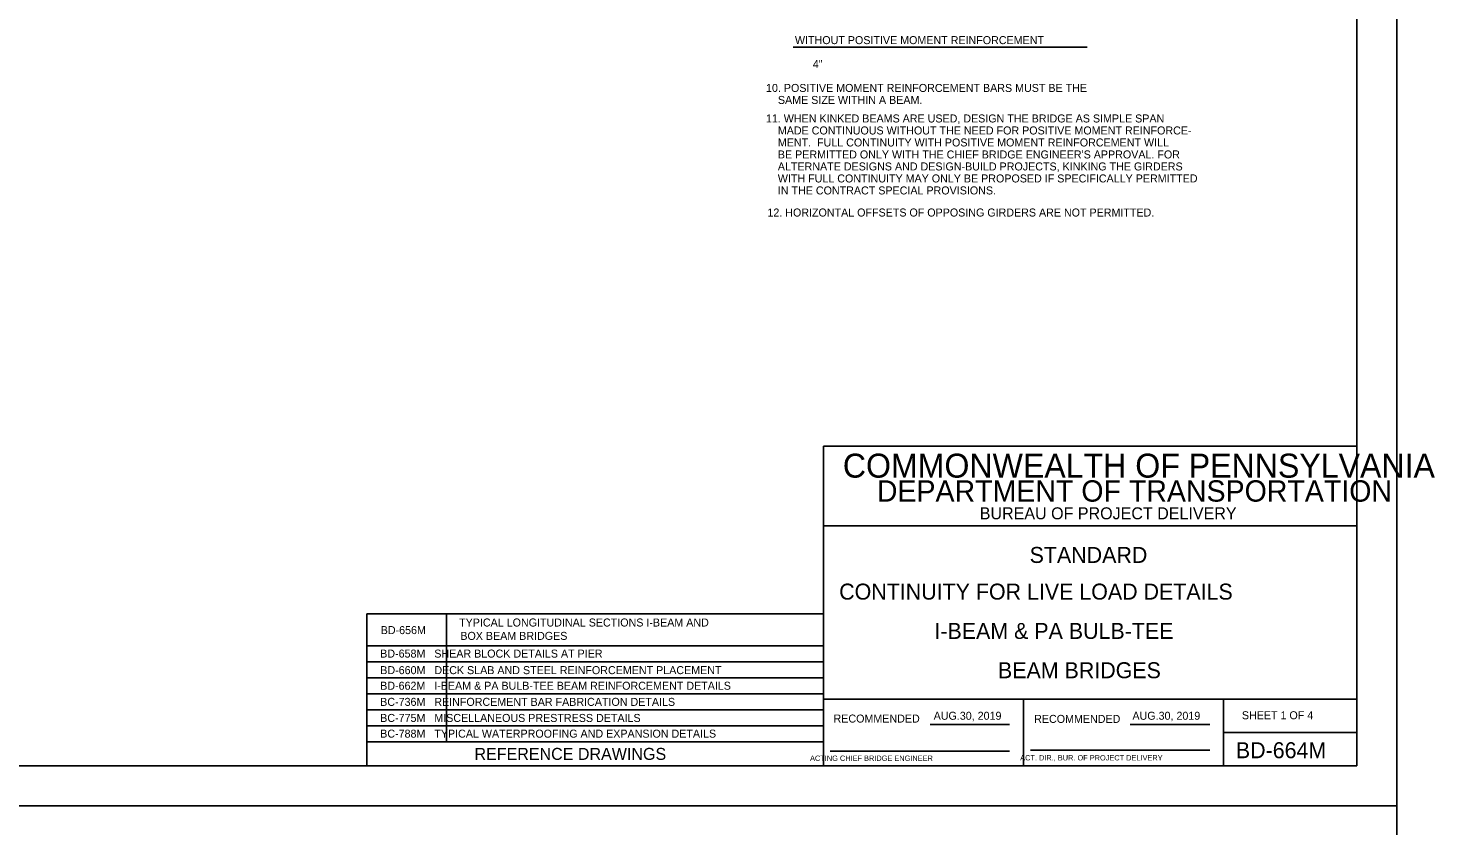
# Model space of a CAD drawing. Extents: x 639980 to 641204, y 298038 to 300414.
# Drawn here: x 640308 to 640836, y 299812 to 300112 of the extents above; entities that cross this region are included whole.
import ezdxf

# ---------------------------------------------------------------- set-up
doc = ezdxf.new("R2010")
doc.units = 0
for name, color, linetype in [('1', 7, 'Continuous'), ('2', 7, 'Continuous'), ('PLT-BNDY', 7, 'Continuous')]:
    doc.layers.add(name, color=color, linetype=linetype)

msp = doc.modelspace()

# ---------------------------------------------------------------- linework, layer by layer
at = {"layer": '2'}
for p, q in [((640806.31, 300398.78), (640806.31, 299834.78)), ((640595, 300104.45), (640705.21, 300104.45)), ((640806.31, 299954.78), (640606.31, 299954.78)), ((640606.31, 299954.78), (640606.31, 299834.78)), ((640806.31, 299834.78), (640806.31, 299954.78)), ((640806.31, 299924.78), (640606.31, 299924.78)), ((640435.1, 299891.78), (640606.31, 299891.78)), ((640435.1, 299891.78), (640435.1, 299834.78)), ((640435.1, 299891.78), (640601.07, 299891.78)), ((640464.97, 299843.78), (640464.97, 299891.78)), ((640435.1, 299879.78), (640606.31, 299879.78)), ((640435.1, 299873.78), (640606.31, 299873.78)), ((640435.1, 299867.78), (640606.31, 299867.78)), ((640435.1, 299861.78), (640606.31, 299861.78)), ((640806.31, 299859.78), (640606.31, 299859.78)), ((640681.31, 299834.78), (640681.31, 299859.78)), ((640756.31, 299859.78), (640756.31, 299834.78)), ((640435.1, 299855.78), (640606.31, 299855.78)), ((640435.1, 299849.78), (640606.31, 299849.78)), ((640646.27, 299850.28), (640676.04, 299850.28)), ((640721.27, 299850.28), (640751.18, 299850.28)), ((640435.1, 299843.78), (640606.31, 299843.78)), ((640756.31, 299847.28), (640806.31, 299847.28)), ((640608.81, 299840.28), (640676.04, 299840.28)), ((640683.93, 299840.66), (640751.18, 299840.66)), ((640806.31, 299834.78), (640020.31, 299834.78)), ((640606.31, 299834.78), (640806.31, 299834.78))]:
    msp.add_line(p, q, dxfattribs=at)
at = {"layer": 'PLT-BNDY'}
for points in [[(639980.31, 300413.78), (640821.31, 300413.78), (640821.31, 299819.78), (639980.31, 299819.78)], [(639980.31, 299819.78), (640821.31, 299819.78), (640821.31, 299225.78), (639980.31, 299225.78)]]:
    msp.add_lwpolyline(points, close=True, dxfattribs=at)

# ---------------------------------------------------------------- texts
at = {"layer": '1'}
for s, height, p in [('WITHOUT POSITIVE MOMENT REINFORCEMENT', 2.9999, (640595.61, 300105.54)), ('      4"', 3, (640595.61, 300096.54))]:
    msp.add_text(s, height=height, dxfattribs=at).set_placement(p)
at = {"layer": '2'}
for s, height, p in [('10. POSITIVE MOMENT REINFORCEMENT BARS MUST BE THE', 3, (640584.76, 300087.6)), ('    SAME SIZE WITHIN A BEAM.', 3, (640584.76, 300083.1)), ('11. WHEN KINKED BEAMS ARE USED, DESIGN THE BRIDGE AS SIMPLE SPAN', 3, (640584.73, 300076.15)), ('    MADE CONTINUOUS WITHOUT THE NEED FOR POSITIVE MOMENT REINFORCE-', 3, (640584.73, 300071.65)), ('    MENT.  FULL CONTINUITY WITH POSITIVE MOMENT REINFORCEMENT WILL', 3, (640584.73, 300067.15)), ("    BE PERMITTED ONLY WITH THE CHIEF BRIDGE ENGINEER'S APPROVAL. FOR", 3, (640584.73, 300062.65)), ('    ALTERNATE DESIGNS AND DESIGN-BUILD PROJECTS, KINKING THE GIRDERS ', 3, (640584.73, 300058.15)), ('    WITH FULL CONTINUITY MAY ONLY BE PROPOSED IF SPECIFICALLY PERMITTED', 3, (640584.73, 300053.65)), ('    IN THE CONTRACT SPECIAL PROVISIONS.', 3, (640584.73, 300049.15)), ('12. HORIZONTAL OFFSETS OF OPPOSING GIRDERS ARE NOT PERMITTED.', 2.9987, (640585.29, 300040.87)), ('COMMONWEALTH OF PENNSYLVANIA', 9, (640613.56, 299942.91)), ('DEPARTMENT OF TRANSPORTATION', 8.0002, (640626.31, 299933.91)), ('BUREAU OF PROJECT DELIVERY', 4.5, (640664.9, 299927.28)), ('STANDARD', 6, (640683.6, 299910.91)), ('CONTINUITY FOR LIVE LOAD DETAILS', 6, (640612.19, 299897.16)), ('BD-656M', 3, (640440.29, 299884.22)), ('TYPICAL LONGITUDINAL SECTIONS I-BEAM AND ', 3, (640469.69, 299887.07)), ('BOX BEAM BRIDGES', 3, (640470.15, 299882.05)), ('I-BEAM & PA BULB-TEE', 6, (640647.91, 299882.41)), ('BD-658M   SHEAR BLOCK DETAILS AT PIER', 3, (640440.1, 299875.41)), ('BD-660M   DECK SLAB AND STEEL REINFORCEMENT PLACEMENT', 3, (640440.12, 299869.2)), ('BEAM BRIDGES', 6, (640671.73, 299867.66)), ('BD-662M   I-BEAM & PA BULB-TEE BEAM REINFORCEMENT DETAILS', 2.9999, (640440.09, 299863.35)), ('BC-736M   REINFORCEMENT BAR FABRICATION DETAILS', 3, (640440.1, 299857.3)), ('BC-775M   MISCELLANEOUS PRESTRESS DETAILS', 3, (640440.1, 299851.27)), ('RECOMMENDED', 3, (640610.08, 299851.03)), ('AUG.30, 2019', 3, (640647.61, 299852.09)), ('RECOMMENDED', 3, (640685.3, 299850.91)), ('AUG.30, 2019', 3, (640722.15, 299852.09)), ('SHEET 1 OF 4', 3, (640763.18, 299852.28)), ('BC-788M   TYPICAL WATERPROOFING AND EXPANSION DETAILS', 3, (640440.1, 299845.38)), ('BD-664M', 6, (640760.93, 299837.66)), ('REFERENCE DRAWINGS', 4.5, (640475.44, 299837.03)), ('       ACTING CHIEF BRIDGE ENGINEER', 2.0002, (640595.9, 299836.66)), ('   ACT. DIR., BUR. OF PROJECT DELIVERY', 2.0002, (640677.76, 299836.83))]:
    msp.add_text(s, height=height, dxfattribs=at).set_placement(p)

doc.saveas('drawing.dxf')
